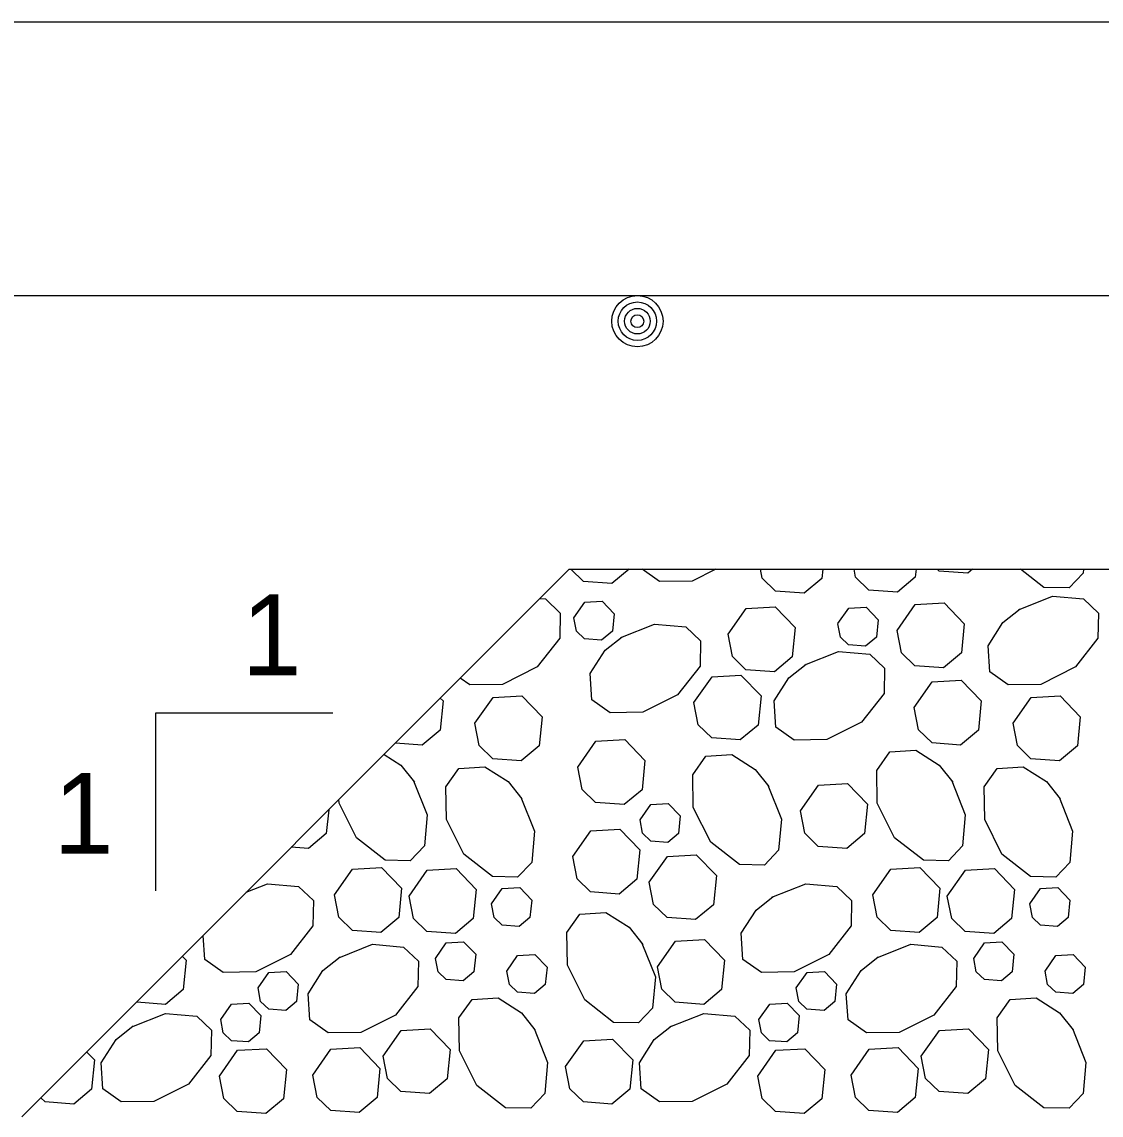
# Model space of a CAD drawing. Extents: x 2084213 to 2099800, y 976677 to 981262.
# Drawn here: x 2095252.4 to 2095383.9, y 979206.9 to 979340 of the extents above; entities that cross this region are included whole.
import ezdxf

# ---------------------------------------------------------------- set-up
doc = ezdxf.new("R2010")
doc.units = 0
doc.layers.add('1', color=7, linetype='Continuous')

msp = doc.modelspace()

# ---------------------------------------------------------------- linework, layer by layer
at = {"layer": '1'}
for p, q in [((2094902.37, 979339.99), (2095499.4, 979339.99)), ((2095019.04, 979306.66), (2095487.58, 979306.66)), ((2095252.38, 979206.67), (2095319.04, 979273.33)), ((2095319.04, 979273.33), (2095499.41, 979273.33)), ((2095268.64, 979255.79), (2095268.64, 979234.18)), ((2095290.25, 979255.79), (2095268.64, 979255.79))]:
    msp.add_line(p, q, dxfattribs=at)
for points in [[(2095326.37, 979273.33), (2095324.27, 979271.58), (2095320.79, 979271.83), (2095319.25, 979273.33)], [(2095336.91, 979273.33), (2095334.04, 979271.89), (2095330.06, 979271.82), (2095327.94, 979273.33)], [(2095349.96, 979273.33), (2095349.85, 979272.22), (2095347.67, 979270.41), (2095344.2, 979270.67), (2095342.56, 979272.25), (2095342.35, 979273.33)], [(2095361.33, 979273.33), (2095361.23, 979272.35), (2095359.05, 979270.54), (2095355.58, 979270.8), (2095353.94, 979272.38), (2095353.76, 979273.33)], [(2095368.19, 979273.33), (2095367.61, 979272.85), (2095364.13, 979273.1), (2095363.89, 979273.33)], [(2095381.71, 979273.33), (2095381.67, 979272.86), (2095379.96, 979271.05), (2095376.88, 979271.11), (2095374.05, 979273.33)], [(2095315.48, 979269.77), (2095316.16, 979269.71), (2095317.96, 979268), (2095317.9, 979264.92), (2095315.17, 979261.43), (2095310.94, 979259.31), (2095306.96, 979259.24), (2095305.79, 979260.08)], [(2095373.82, 979268.4), (2095377.95, 979270.04), (2095381.74, 979269.71), (2095383.54, 979268), (2095383.48, 979264.92), (2095380.75, 979261.43), (2095376.52, 979259.31), (2095372.54, 979259.24), (2095370.3, 979260.84), (2095370.09, 979264.01), (2095371.91, 979266.85), (2095373.99, 979268.51)], [(2095319.63, 979267.43), (2095320.95, 979269.31), (2095323.06, 979269.43), (2095324.53, 979267.91), (2095324.32, 979265.78), (2095323.01, 979264.69), (2095320.93, 979264.84), (2095319.95, 979265.79), (2095319.63, 979267.43)], [(2095338.41, 979265.41), (2095340.62, 979268.55), (2095344.14, 979268.75), (2095346.59, 979266.22), (2095346.23, 979262.66), (2095344.06, 979260.85), (2095340.58, 979261.1), (2095338.94, 979262.69), (2095338.41, 979265.41)], [(2095351.79, 979266.71), (2095353.12, 979268.59), (2095355.23, 979268.71), (2095356.7, 979267.18), (2095356.49, 979265.05), (2095355.18, 979263.97), (2095353.09, 979264.12), (2095352.11, 979265.07), (2095351.79, 979266.7)], [(2095359.02, 979265.89), (2095361.23, 979269.03), (2095364.75, 979269.23), (2095367.2, 979266.69), (2095366.84, 979263.14), (2095364.67, 979261.33), (2095361.19, 979261.58), (2095359.55, 979263.16), (2095359.02, 979265.89)], [(2095325.34, 979265.01), (2095329.47, 979266.65), (2095333.26, 979266.32), (2095335.06, 979264.61), (2095335, 979261.53), (2095332.27, 979258.04), (2095328.04, 979255.93), (2095324.06, 979255.86), (2095321.82, 979257.45), (2095321.61, 979260.62), (2095323.43, 979263.46), (2095325.51, 979265.12)], [(2095347.76, 979261.68), (2095351.88, 979263.31), (2095355.68, 979262.99), (2095357.48, 979261.27), (2095357.42, 979258.2), (2095354.68, 979254.7), (2095350.46, 979252.59), (2095346.48, 979252.52), (2095344.23, 979254.11), (2095344.02, 979257.29), (2095345.84, 979260.12), (2095347.93, 979261.78)], [(2095334.26, 979257.11), (2095336.47, 979260.25), (2095339.99, 979260.45), (2095342.44, 979257.91), (2095342.08, 979254.36), (2095339.91, 979252.55), (2095336.43, 979252.8), (2095334.79, 979254.39), (2095334.26, 979257.11)], [(2095361.1, 979256.5), (2095363.3, 979259.64), (2095366.82, 979259.84), (2095369.27, 979257.3), (2095368.92, 979253.74), (2095366.74, 979251.93), (2095363.27, 979252.18), (2095361.63, 979253.77), (2095361.1, 979256.5)], [(2095303.36, 979257.65), (2095303.69, 979257.3), (2095303.34, 979253.74), (2095301.16, 979251.93), (2095297.88, 979252.17)], [(2095307.58, 979254.58), (2095309.78, 979257.71), (2095313.3, 979257.92), (2095315.75, 979255.38), (2095315.4, 979251.82), (2095313.22, 979250.01), (2095309.75, 979250.26), (2095308.11, 979251.85), (2095307.58, 979254.58)], [(2095373.16, 979254.58), (2095375.36, 979257.71), (2095378.88, 979257.92), (2095381.33, 979255.38), (2095380.98, 979251.82), (2095378.8, 979250.01), (2095375.32, 979250.26), (2095373.69, 979251.85), (2095373.16, 979254.58)], [(2095320.12, 979249.24), (2095322.32, 979252.38), (2095325.84, 979252.58), (2095328.29, 979250.04), (2095327.94, 979246.49), (2095325.76, 979244.68), (2095322.28, 979244.93), (2095320.65, 979246.52), (2095320.12, 979249.24)], [(2095365.69, 979247.56), (2095367.32, 979243.43), (2095366.99, 979239.64), (2095365.28, 979237.84), (2095362.21, 979237.9), (2095358.71, 979240.63), (2095356.6, 979244.86), (2095356.53, 979248.84), (2095358.12, 979251.08), (2095361.29, 979251.3), (2095364.13, 979249.48), (2095365.79, 979247.39)], [(2095296.5, 979250.79), (2095298.55, 979249.48), (2095300.21, 979247.39)], [(2095343.27, 979247.03), (2095344.91, 979242.9), (2095344.58, 979239.11), (2095342.87, 979237.31), (2095339.79, 979237.37), (2095336.3, 979240.1), (2095334.18, 979244.33), (2095334.11, 979248.31), (2095335.7, 979250.55), (2095338.88, 979250.76), (2095341.71, 979248.94), (2095343.38, 979246.86)], [(2095313.18, 979245.56), (2095314.82, 979241.43), (2095314.49, 979237.64), (2095312.78, 979235.84), (2095309.7, 979235.9), (2095306.21, 979238.63), (2095304.1, 979242.86), (2095304.03, 979246.84), (2095305.62, 979249.08), (2095308.79, 979249.29), (2095311.63, 979247.48), (2095313.29, 979245.39)], [(2095378.76, 979245.56), (2095380.4, 979241.43), (2095380.07, 979237.64), (2095378.36, 979235.84), (2095375.28, 979235.9), (2095371.79, 979238.63), (2095369.68, 979242.86), (2095369.61, 979246.84), (2095371.2, 979249.08), (2095374.37, 979249.29), (2095377.21, 979247.48), (2095378.87, 979245.39)], [(2095300.11, 979247.56), (2095301.74, 979243.43), (2095301.42, 979239.64), (2095299.7, 979237.84), (2095296.63, 979237.9), (2095293.13, 979240.63), (2095291.02, 979244.86), (2095291.01, 979245.3)], [(2095347.23, 979243.91), (2095349.44, 979247.04), (2095352.96, 979247.24), (2095355.41, 979244.71), (2095355.05, 979241.15), (2095352.88, 979239.34), (2095349.4, 979239.59), (2095347.77, 979241.18), (2095347.23, 979243.91)], [(2095327.69, 979242.81), (2095329.02, 979244.7), (2095331.13, 979244.82), (2095332.6, 979243.29), (2095332.39, 979241.16), (2095331.08, 979240.07), (2095329, 979240.23), (2095328.01, 979241.18), (2095327.7, 979242.81)], [(2095289.76, 979244.05), (2095289.47, 979241.15), (2095287.3, 979239.34), (2095285.2, 979239.49)], [(2095319.5, 979238.35), (2095321.7, 979241.48), (2095325.23, 979241.69), (2095327.67, 979239.15), (2095327.32, 979235.59), (2095325.14, 979233.78), (2095321.67, 979234.03), (2095320.03, 979235.62), (2095319.5, 979238.35)], [(2095328.82, 979235.23), (2095331.02, 979238.37), (2095334.55, 979238.57), (2095336.99, 979236.03), (2095336.64, 979232.48), (2095334.46, 979230.67), (2095330.99, 979230.92), (2095329.35, 979232.5), (2095328.82, 979235.23)], [(2095290.48, 979233.68), (2095292.68, 979236.82), (2095296.21, 979237.02), (2095298.65, 979234.48), (2095298.3, 979230.92), (2095296.12, 979229.11), (2095292.65, 979229.36), (2095291.01, 979230.95), (2095290.48, 979233.68)], [(2095299.55, 979233.54), (2095301.76, 979236.68), (2095305.28, 979236.88), (2095307.73, 979234.34), (2095307.37, 979230.79), (2095305.2, 979228.98), (2095301.72, 979229.23), (2095300.09, 979230.82), (2095299.55, 979233.54)], [(2095356.06, 979233.68), (2095358.26, 979236.82), (2095361.79, 979237.02), (2095364.23, 979234.48), (2095363.88, 979230.92), (2095361.7, 979229.11), (2095358.23, 979229.36), (2095356.59, 979230.95), (2095356.06, 979233.68)], [(2095365.13, 979233.54), (2095367.34, 979236.68), (2095370.86, 979236.88), (2095373.31, 979234.34), (2095372.95, 979230.79), (2095370.78, 979228.98), (2095367.3, 979229.23), (2095365.67, 979230.82), (2095365.13, 979233.54)], [(2095279.71, 979234), (2095282.3, 979235.03), (2095286.09, 979234.7), (2095287.89, 979232.99), (2095287.84, 979229.91), (2095285.1, 979226.42), (2095280.88, 979224.3), (2095276.9, 979224.23), (2095274.65, 979225.83), (2095274.46, 979228.75)], [(2095343.76, 979233.39), (2095347.88, 979235.03), (2095351.67, 979234.7), (2095353.47, 979232.99), (2095353.42, 979229.91), (2095350.68, 979226.42), (2095346.46, 979224.3), (2095342.47, 979224.23), (2095340.23, 979225.83), (2095340.02, 979229), (2095341.84, 979231.83), (2095343.92, 979233.5)], [(2095309.59, 979232.58), (2095310.91, 979234.46), (2095313.03, 979234.58), (2095314.49, 979233.05), (2095314.28, 979230.92), (2095312.98, 979229.84), (2095310.89, 979229.99), (2095309.91, 979230.94), (2095309.59, 979232.57)], [(2095375.17, 979232.58), (2095376.49, 979234.46), (2095378.61, 979234.58), (2095380.07, 979233.05), (2095379.86, 979230.92), (2095378.56, 979229.84), (2095376.47, 979229.99), (2095375.49, 979230.94), (2095375.17, 979232.57)], [(2095327.92, 979227.81), (2095329.56, 979223.69), (2095329.23, 979219.9), (2095327.52, 979218.1), (2095324.44, 979218.15), (2095320.95, 979220.89), (2095318.84, 979225.11), (2095318.77, 979229.09), (2095320.36, 979231.34), (2095323.53, 979231.55), (2095326.37, 979229.73), (2095328.03, 979227.65)], [(2095290.98, 979226.02), (2095295.1, 979227.66), (2095298.89, 979227.33), (2095300.7, 979225.62), (2095300.64, 979222.54), (2095297.9, 979219.04), (2095293.68, 979216.93), (2095289.7, 979216.86), (2095287.46, 979218.45), (2095287.24, 979221.63), (2095289.06, 979224.46), (2095291.14, 979226.13)], [(2095302.76, 979225.95), (2095304.09, 979227.84), (2095306.2, 979227.96), (2095307.67, 979226.44), (2095307.46, 979224.3), (2095306.15, 979223.22), (2095304.06, 979223.37), (2095303.08, 979224.32), (2095302.76, 979225.95)], [(2095329.8, 979224.91), (2095332.01, 979228.05), (2095335.53, 979228.25), (2095337.98, 979225.71), (2095337.62, 979222.15), (2095335.45, 979220.34), (2095331.97, 979220.6), (2095330.33, 979222.18), (2095329.8, 979224.91)], [(2095356.56, 979226.02), (2095360.68, 979227.66), (2095364.47, 979227.33), (2095366.28, 979225.62), (2095366.22, 979222.54), (2095363.48, 979219.04), (2095359.26, 979216.93), (2095355.28, 979216.86), (2095353.03, 979218.45), (2095352.82, 979221.63), (2095354.64, 979224.46), (2095356.72, 979226.13)], [(2095368.34, 979225.95), (2095369.66, 979227.84), (2095371.78, 979227.96), (2095373.25, 979226.44), (2095373.03, 979224.3), (2095371.73, 979223.22), (2095369.64, 979223.37), (2095368.66, 979224.32), (2095368.34, 979225.95)], [(2095271.92, 979226.21), (2095272.4, 979225.71), (2095272.04, 979222.15), (2095269.87, 979220.34), (2095266.39, 979220.6), (2095266.35, 979220.64)], [(2095311.45, 979224.4), (2095312.77, 979226.29), (2095314.89, 979226.41), (2095316.36, 979224.88), (2095316.14, 979222.75), (2095314.84, 979221.66), (2095312.75, 979221.82), (2095311.77, 979222.77), (2095311.45, 979224.4)], [(2095377.03, 979224.4), (2095378.35, 979226.29), (2095380.47, 979226.41), (2095381.94, 979224.88), (2095381.72, 979222.75), (2095380.42, 979221.66), (2095378.33, 979221.82), (2095377.35, 979222.77), (2095377.03, 979224.4)], [(2095281.15, 979222.34), (2095282.47, 979224.22), (2095284.58, 979224.34), (2095286.05, 979222.82), (2095285.84, 979220.68), (2095284.53, 979219.6), (2095282.45, 979219.75), (2095281.47, 979220.7), (2095281.15, 979222.34)], [(2095346.73, 979222.34), (2095348.05, 979224.22), (2095350.16, 979224.34), (2095351.63, 979222.82), (2095351.42, 979220.68), (2095350.11, 979219.6), (2095348.03, 979219.75), (2095347.05, 979220.7), (2095346.73, 979222.34)], [(2095276.6, 979218.51), (2095277.92, 979220.39), (2095280.03, 979220.51), (2095281.5, 979218.99), (2095281.29, 979216.86), (2095279.98, 979215.77), (2095277.9, 979215.92), (2095276.92, 979216.87), (2095276.6, 979218.51)], [(2095314.78, 979217.4), (2095316.42, 979213.28), (2095316.09, 979209.49), (2095314.38, 979207.69), (2095311.3, 979207.74), (2095307.81, 979210.48), (2095305.7, 979214.7), (2095305.63, 979218.69), (2095307.22, 979220.93), (2095310.39, 979221.14), (2095313.23, 979219.32), (2095314.89, 979217.24)], [(2095342.17, 979218.51), (2095343.5, 979220.39), (2095345.61, 979220.51), (2095347.08, 979218.99), (2095346.87, 979216.86), (2095345.56, 979215.77), (2095343.48, 979215.92), (2095342.49, 979216.87), (2095342.18, 979218.51)], [(2095380.36, 979217.4), (2095382, 979213.28), (2095381.67, 979209.49), (2095379.96, 979207.69), (2095376.88, 979207.74), (2095373.39, 979210.48), (2095371.28, 979214.7), (2095371.21, 979218.69), (2095372.8, 979220.93), (2095375.97, 979221.14), (2095378.81, 979219.32), (2095380.47, 979217.24)], [(2095265.76, 979217.61), (2095269.89, 979219.25), (2095273.68, 979218.92), (2095275.48, 979217.21), (2095275.42, 979214.13), (2095272.69, 979210.64), (2095268.46, 979208.53), (2095264.48, 979208.46), (2095262.24, 979210.05), (2095262.03, 979213.22), (2095263.85, 979216.06), (2095265.93, 979217.72)], [(2095331.34, 979217.61), (2095335.47, 979219.25), (2095339.26, 979218.92), (2095341.06, 979217.21), (2095341, 979214.13), (2095338.27, 979210.64), (2095334.04, 979208.53), (2095330.06, 979208.46), (2095327.82, 979210.05), (2095327.61, 979213.22), (2095329.43, 979216.06), (2095331.51, 979217.72)], [(2095296.38, 979214.04), (2095298.59, 979217.18), (2095302.11, 979217.38), (2095304.56, 979214.84), (2095304.2, 979211.29), (2095302.03, 979209.48), (2095298.55, 979209.73), (2095296.92, 979211.32), (2095296.38, 979214.04)], [(2095361.96, 979214.04), (2095364.17, 979217.18), (2095367.69, 979217.38), (2095370.14, 979214.84), (2095369.78, 979211.29), (2095367.61, 979209.48), (2095364.13, 979209.73), (2095362.49, 979211.32), (2095361.96, 979214.04)], [(2095287.83, 979211.74), (2095290.03, 979214.88), (2095293.56, 979215.08), (2095296, 979212.54), (2095295.65, 979208.99), (2095293.47, 979207.18), (2095290, 979207.43), (2095288.36, 979209.02), (2095287.83, 979211.74)], [(2095318.62, 979212.78), (2095320.83, 979215.92), (2095324.35, 979216.12), (2095326.8, 979213.58), (2095326.44, 979210.02), (2095324.27, 979208.21), (2095320.79, 979208.46), (2095319.15, 979210.05), (2095318.62, 979212.78)], [(2095353.41, 979211.74), (2095355.61, 979214.88), (2095359.13, 979215.08), (2095361.58, 979212.54), (2095361.23, 979208.99), (2095359.05, 979207.18), (2095355.58, 979207.43), (2095353.94, 979209.02), (2095353.41, 979211.74)], [(2095260.27, 979214.56), (2095261.22, 979213.58), (2095260.86, 979210.02), (2095258.69, 979208.21), (2095255.21, 979208.46), (2095254.69, 979208.97)], [(2095276.45, 979211.61), (2095278.65, 979214.75), (2095282.18, 979214.95), (2095284.62, 979212.41), (2095284.27, 979208.86), (2095282.09, 979207.05), (2095278.62, 979207.3), (2095276.98, 979208.89), (2095276.45, 979211.61)], [(2095342.03, 979211.61), (2095344.23, 979214.75), (2095347.76, 979214.95), (2095350.2, 979212.41), (2095349.85, 979208.86), (2095347.67, 979207.05), (2095344.2, 979207.3), (2095342.56, 979208.89), (2095342.03, 979211.61)]]:
    msp.add_lwpolyline(points, dxfattribs=at)
for radius in [3.12, 2.34, 1.56, 0.781]:
    msp.add_circle((2095327.37, 979303.54), radius, dxfattribs=at)

# ---------------------------------------------------------------- texts
for p in [(2095279.16, 979260.43), (2095256.23, 979238.68)]:
    msp.add_text('1', height=9.84, dxfattribs=at).set_placement(p)

doc.saveas('drawing.dxf')
